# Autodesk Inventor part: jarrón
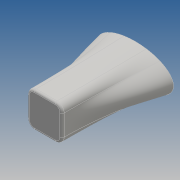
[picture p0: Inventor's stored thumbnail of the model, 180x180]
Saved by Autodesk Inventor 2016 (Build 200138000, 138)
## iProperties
Created: 2015-08
Part Number: jarrón
Material: Generic
Document SubType Name: Modeling
Designer: julian.chica
Density: 1 g/cm^3
Appearance: Default
Author: julian.chica
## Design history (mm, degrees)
sketch "Sketch1"
  geometry: L1 (15, 25)-(-15, 25); L2 (-25, 15)-(-25, -15); L3 (-15, -25)-(15, -25); L4 (25, -15)-(25, 15); L5 (25, 25)-(-25, -25); L6 (-25, 25)-(25, -25); A1 r 10 centre (15, -15) between (15, -25) and (25, -15); A2 r 10 centre (15, 15) between (25, 15) and (15, 25); A3 r 10 centre (-15, 15) between (-15, 25) and (-25, 15); A4 r 10 centre (-15, -15) between (-25, -15) and (-15, -25); 1 further point
  constraints: 12 end point, 8 point on circle, 8 point on line, 8 tangent, 4 centre point, 3 equal radius, 2 midpoint, 2 parallel, 1 horizontal, 1 perpendicular
  dimensions: "d0" = 50 distance of L6.end L5.end; "d1" = 50 distance of L5.end L6.start; "d2" = 10 radius of A1
workplane "Work Plane1"
sketch "Sketch2" dims "d4" = 55, "d5" = 28
  geometry: L1 (-44.741, 16.285)-(44.741, -16.285); L2 (77, 0)-(-77, 0) reference; L3 (-44.741, -16.285)-(44.741, 16.285); L4 (-21.606, -25.749)-(21.606, 25.749); L5 (-21.606, 25.749)-(21.606, -25.749); 3 further points; 8 other entities
  constraints: 8 end point, 4 midpoint, 2 coincident, 32 other
  dimensions: "d6" = 20 deg angle of L1 L2; "d7" = 20 deg angle of L3 L2; "d8" = 50 deg angle of L2 L4; "d9" = 50 deg angle of L2 L5
loft "Loft1" sketch "Sketch2" dims "d10" = 10, "d11" = 90 deg, "d12" = 0, "d13" = 90 deg
fillet "Fillet1" dims "d14" = 3
shell "Shell1" dims "d15" = 1.7
body "Solid1"
